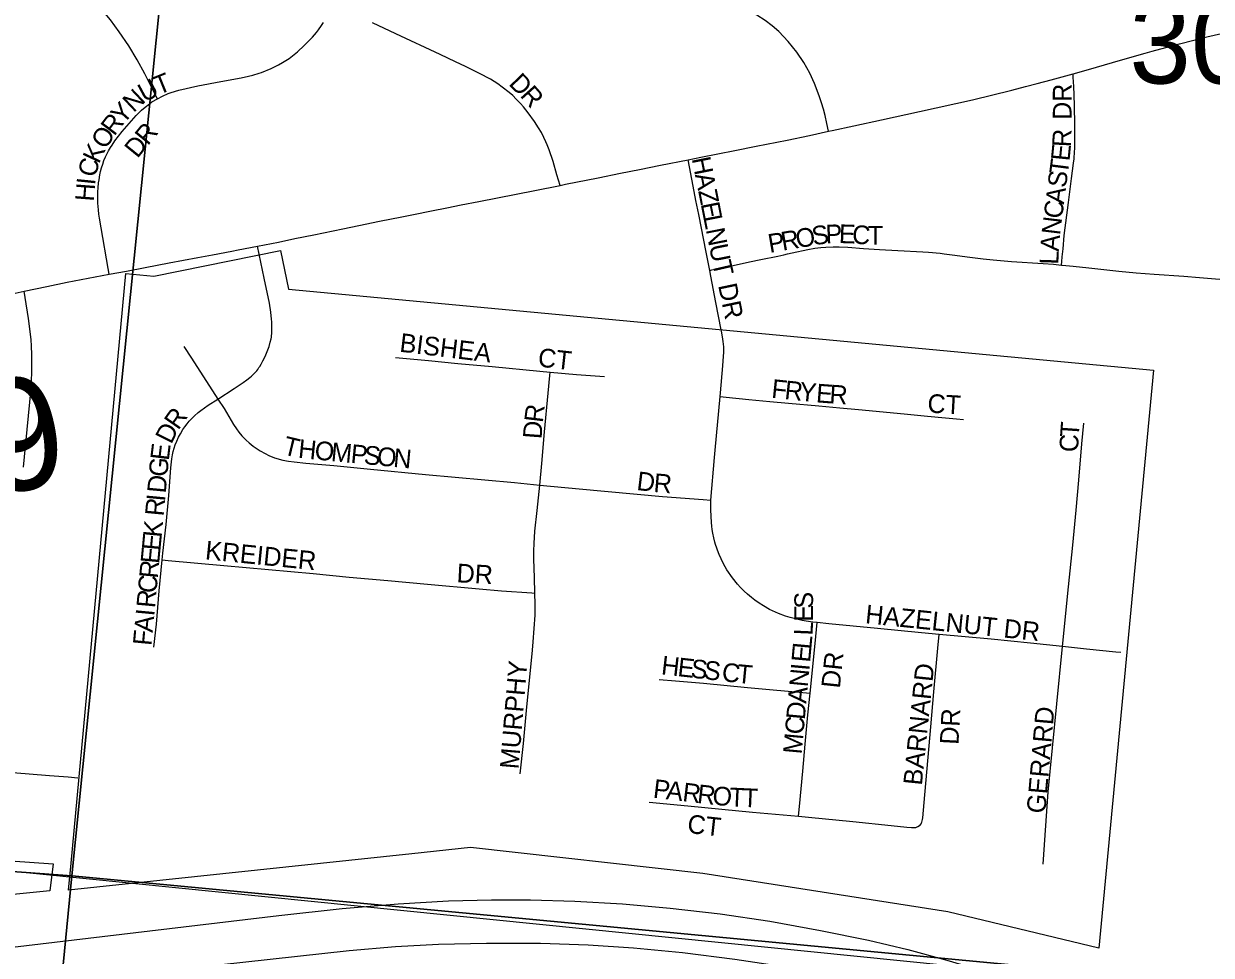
# Model space of a CAD drawing. Extents: x 1410790 to 1770854, y 448063 to 770588.
# Drawn here: x 1535008 to 1538182, y 650649 to 653140 of the extents above; entities that cross this region are included whole.
import ezdxf

# ---------------------------------------------------------------- set-up
doc = ezdxf.new("R2010")
doc.units = 0
for name, color, linetype in [('GM_X_City_Street', 7, 'Continuous'), ('GM_X_City_Street_Text', 7, 'Continuous'), ('GM_X_Corporation', 7, 'Continuous'), ('GM_X_Interstate_Route', 7, 'Continuous'), ('GM_X_Section', 7, 'Continuous'), ('GM_X_Section_Text', 7, 'Continuous'), ('GM_X_Township', 7, 'Continuous'), ('GM_X_Township_Road', 7, 'Continuous'), ('GM_X_Township_Road_Text', 7, 'Continuous'), ('GM_X_Township_Subdivision', 7, 'Continuous'), ('GM_X_Township_Subdivision_Text', 7, 'Continuous')]:
    doc.layers.add(name, color=color, linetype=linetype)

msp = doc.modelspace()

# ---------------------------------------------------------------- linework, layer by layer
at = {"layer": 'GM_X_City_Street'}
for points in [[(1535526.4, 652136.1), (1535569.7, 652164.1), (1535593.9, 652180.3), (1535604.1, 652187.5), (1535612, 652193.4), (1535616.8, 652197.5), (1535622.5, 652203.1), (1535626.4, 652207.4), (1535630.4, 652211.9), (1535632.9, 652215.2), (1535636.4, 652220.1), (1535638.5, 652223.2), (1535642.4, 652229.6), (1535646.9, 652238.3), (1535652.6, 652250), (1535658.5, 652263.3), (1535663.3, 652276.3), (1535666.4, 652287.9), (1535668.8, 652297.4), (1535669.6, 652301.5), (1535670.3, 652306.1), (1535670.7, 652310.2), (1535671.2, 652321.5), (1535671.2, 652328.8), (1535670.6, 652343), (1535670.1, 652349.7), (1535668.1, 652368.1), (1535664.2, 652392.4), (1535650.5, 652458.9), (1535632.2, 652544.9)], [(1536868.9, 652142.8), (1536869.9, 652152.8), (1536876.5, 652225.1), (1536878.1, 652250.8), (1536878.6, 652260.5), (1536878.8, 652267.8), (1536878.8, 652275.5), (1536878.2, 652283.1), (1536877.5, 652290.1), (1536876.7, 652296.3), (1536874.9, 652308), (1536873.2, 652317.4), (1536872.3, 652321.4)], [(1535435.2, 652276.8), (1535455.7, 652245.5), (1535526.4, 652136.1)], [(1536000.9, 652247.4), (1536089.6, 652239), (1536167.9, 652230.9), (1536259.5, 652222.7), (1536387.1, 652210.8), (1536414.8, 652208.1)], [(1536386.9, 651906.3), (1536392.4, 651963.7), (1536399.8, 652048.4), (1536409.5, 652151.6), (1536414, 652199.2), (1536414.8, 652208.1)], [(1536414.8, 652208.1), (1536485.2, 652201.3), (1536560, 652196)], [(1535378, 651705.8), (1535379.8, 651724.2), (1535388, 651801.1), (1535395.2, 651877.9), (1535401.1, 651952.4), (1535403.5, 651975.9), (1535405.1, 651986.6), (1535407.1, 651996), (1535409.6, 652005.1), (1535412.6, 652014), (1535416.7, 652023.9), (1535421.6, 652034.3), (1535426.4, 652043.3), (1535433.1, 652054.5), (1535438.2, 652062.1), (1535444.3, 652070.1), (1535450.1, 652076.9), (1535456.9, 652084.2), (1535464.4, 652091.3), (1535474, 652099.7), (1535480.9, 652105.1), (1535500.9, 652119.6), (1535526.4, 652136.1)], [(1535526.4, 652136.1), (1535543, 652110.5), (1535568.5, 652068.4), (1535576.1, 652056.8), (1535582.7, 652047.8), (1535590.8, 652038.2), (1535602.4, 652025.9), (1535610, 652018.9), (1535620.6, 652010.1), (1535639.6, 651997.3), (1535652.6, 651990.2), (1535662.3, 651985.6), (1535678.1, 651979.1), (1535700.1, 651972.6), (1535715.5, 651970), (1535730.3, 651968.1), (1535761.8, 651964.9), (1535836.8, 651958.2), (1535934.6, 651948.6), (1536081.4, 651934.5), (1536319.7, 651912.9), (1536386.9, 651906.3)], [(1536844.7, 651865.6), (1536854.2, 651979.6), (1536855.6, 651999.2), (1536868.9, 652142.8)], [(1536868.9, 652142.8), (1536885, 652141.2), (1536945.9, 652135), (1537002, 652129.5), (1537051.9, 652125), (1537132.6, 652117.7), (1537189.1, 652112.5), (1537239.2, 652108), (1537360.8, 652096.2), (1537423.3, 652090.2), (1537471.6, 652085.6), (1537500.6, 652083.1), (1537520.1, 652081.5)], [(1537783.9, 651474.4), (1537800.6, 651633.8), (1537812.1, 651745.8), (1537821.3, 651838.8), (1537827.9, 651919.1), (1537836.2, 652016.2), (1537841.2, 652071.6)], [(1536374.1, 651617.3), (1536372.8, 651658.6), (1536371.1, 651708.1), (1536371.4, 651730.5), (1536372.1, 651749.7), (1536374.1, 651783.1), (1536379.9, 651838.4), (1536386.9, 651906.3)], [(1536386.9, 651906.3), (1536492.7, 651896.4), (1536714.9, 651875.8), (1536823.6, 651867.1), (1536844.7, 651865.6)], [(1537128.5, 651538.7), (1537116.7, 651540), (1537098.8, 651542.5), (1537088, 651544.4), (1537070.8, 651548.1), (1537056.6, 651551.8), (1537043.5, 651555.8), (1537025, 651562.5), (1537001.3, 651573.5), (1536984.8, 651583.1), (1536973.6, 651590.1), (1536962.1, 651598.2), (1536952.7, 651605.5), (1536942.2, 651614.3), (1536933.5, 651622.3), (1536923.9, 651632.2), (1536915.3, 651641.6), (1536902.1, 651657.9), (1536887.3, 651679.5), (1536878.3, 651695.7), (1536871.8, 651708.8), (1536866.6, 651720.3), (1536862, 651731.7), (1536860, 651737.5), (1536857, 651746.8), (1536855.1, 651753.6), (1536852.4, 651765.3), (1536849.9, 651777.6), (1536848.2, 651787.4), (1536847, 651796.5), (1536846, 651806.1), (1536845, 651822.9), (1536844.5, 651839.7), (1536844.7, 651865.6)], [(1535355.6, 651472.5), (1535362.2, 651534.6), (1535369.9, 651622.9), (1535378, 651705.8)], [(1535378, 651705.8), (1535393.2, 651704.4), (1535542.2, 651691.2), (1535781.4, 651669.4), (1535877.7, 651660.3), (1535980.9, 651650.7), (1536086.7, 651641.2), (1536224.8, 651628.6), (1536284.3, 651623.5), (1536365.4, 651617.9), (1536374.1, 651617.3)], [(1536335, 651133.8), (1536343.7, 651215.3), (1536352.4, 651313.2), (1536361.4, 651401.3), (1536367.6, 651464.5), (1536369.5, 651486.8), (1536374.4, 651557.9), (1536375, 651587.3), (1536374.1, 651617.3)], [(1537109.6, 651349.7), (1537123.1, 651482.8), (1537126.7, 651519.6), (1537128.5, 651538.7)], [(1537454.3, 651506.5), (1537407.8, 651510.7), (1537290.2, 651522.6), (1537159.6, 651535.4), (1537128.5, 651538.7)], [(1537401.7, 650995.5), (1537403.7, 650997.2), (1537405.5, 650999.1), (1537406.5, 651000.7), (1537407.6, 651002.7), (1537408.5, 651005.2), (1537409.4, 651008.5), (1537410, 651012), (1537410.6, 651016), (1537414.5, 651057.7), (1537432.8, 651259.5), (1537440.8, 651353.1), (1537450.8, 651469.7), (1537454.3, 651506.5)], [(1537783.9, 651474.4), (1537698.5, 651483.5), (1537594, 651493.7), (1537454.3, 651506.5)], [(1537733, 650892.5), (1537746.4, 651085.5), (1537769.3, 651320.9), (1537783.9, 651474.4)], [(1537940, 651458.5), (1537926.9, 651459.6), (1537848.6, 651467.5), (1537783.9, 651474.4)], [(1536706.5, 651385.9), (1536750, 651383), (1536825, 651376.5), (1536942.4, 651365.1), (1537109.6, 651349.7)], [(1537078.2, 651020.8), (1537080.9, 651047), (1537090.5, 651141.3), (1537096.7, 651213.1), (1537103.8, 651291.4), (1537109.6, 651349.7)], [(1536679.7, 651058.3), (1536782.4, 651048.9), (1536873.6, 651039.3), (1536955.4, 651031.9), (1537078.2, 651020.8)], [(1537078.2, 651020.8), (1537105.8, 651018.3), (1537223.5, 651006.9), (1537326.1, 650995.7), (1537368.2, 650991.3), (1537380.4, 650990.3), (1537384.4, 650990.2), (1537388.2, 650990.4), (1537391.9, 650991), (1537394.4, 650991.6), (1537397.9, 650993.2), (1537401.7, 650995.5)]]:
    msp.add_lwpolyline(points, dxfattribs=at)
at = {"layer": 'GM_X_Corporation'}
msp.add_lwpolyline([(1535134.4, 650895.6), (1535280.8, 652471.8), (1535355.4, 652465), (1535694.3, 652533.1), (1535715.1, 652429.8), (1538027.5, 652213.4), (1537881.7, 650667.7), (1537477.9, 650765.2), (1536822.5, 650867.2), (1536201.7, 650937.2), (1536044.9, 650920.6), (1535127.2, 650822.9)], close=True, dxfattribs=at)
msp.add_lwpolyline([(1533375, 651013.4), (1535085.8, 650893.5), (1535077.7, 650821.6), (1534880.1, 650801.4)], dxfattribs=at)
at = {"layer": 'GM_X_Interstate_Route'}
for points in [[(1534796.3, 650649.1), (1535689.1, 650755.7), (1535858.6, 650774.1), (1536008.9, 650786.7), (1536143.1, 650794.3), (1536257.8, 650797.6), (1536362.6, 650797.5), (1536480.5, 650793.9), (1536608.1, 650786.4), (1536735.4, 650775.2), (1536868.9, 650759.5), (1537001.8, 650739.7), (1537137.3, 650715.6), (1537265.7, 650688.9), (1537370.9, 650664), (1537475.3, 650636), (1537623.1, 650592.3), (1537946.2, 650493.1), (1538445.7, 650342.1)], [(1533567.9, 650397.8), (1534167.2, 650465), (1534384.7, 650489.3), (1534681.1, 650525), (1535108, 650573.5), (1535528.1, 650623.8), (1535877.1, 650661.6), (1536001.4, 650672.3), (1536116.2, 650678.7), (1536244.2, 650681.6), (1536388.6, 650681), (1536516.6, 650676.7), (1536637.9, 650669), (1536768.6, 650656.3), (1536908.7, 650638.8), (1537045, 650617.8), (1537167.7, 650595.3), (1537260.8, 650575.3), (1537375.5, 650546.6), (1537517.7, 650506.4), (1537881.9, 650396.3), (1538287.2, 650274.9)]]:
    msp.add_lwpolyline(points, dxfattribs=at)
at = {"layer": 'GM_X_Section'}
for points in [[(1535655.6, 656010.7), (1535136.5, 650861.1), (1529818.7, 651249.1), (1530308.8, 656571.2)], [(1540980.4, 655448.5), (1541102.2, 655436.4), (1540640, 650339.9), (1535136.5, 650861.1), (1535655.6, 656010.7)], [(1535136.5, 650861.1), (1534609.1, 645459.7), (1529389.2, 645957.9), (1529818.7, 651249.1)], [(1540640, 650339.9), (1540107.2, 644974.6), (1534609.1, 645459.7), (1535136.5, 650861.1)]]:
    msp.add_lwpolyline(points, close=True, dxfattribs=at)
at = {"layer": 'GM_X_Township'}
for points in [[(1521201.8, 673511.2), (1520708.9, 668234.8), (1520705, 668192.8), (1520384.1, 664777), (1520023.3, 660938), (1519813.3, 658702.6), (1519702.8, 657525.8), (1519766.8, 657522.5), (1519720.6, 657004.8), (1519314.6, 652452.1), (1524688.8, 651910.7), (1526106.4, 651767.9), (1530096, 651366), (1531112.1, 651263.6), (1532044.4, 651169.7), (1532157.4, 651158.4), (1532426.7, 651131.2), (1533590, 651014), (1540632, 650304.6), (1541201.9, 650247.2), (1548862.1, 649478.6)], [(1518591.2, 644339.7), (1518813, 646827.1), (1519006.1, 648972.3), (1519314.6, 652452.1), (1524688.8, 651910.7), (1526106.4, 651767.9), (1530096, 651366), (1531112.1, 651263.6), (1532044.4, 651169.7), (1532157.4, 651158.4), (1532426.7, 651131.2), (1533590, 651014), (1540632, 650304.6), (1541201.9, 650247.2), (1548862.1, 649478.6), (1553877.2, 648970.1), (1556492.4, 648706.9), (1556030.2, 643461.3)]]:
    msp.add_lwpolyline(points, dxfattribs=at)
at = {"layer": 'GM_X_Township_Road'}
for points in [[(1537812.8, 653005.2), (1537841.8, 653013.7), (1537875.6, 653023.8), (1537939.1, 653042), (1538005, 653060.6), (1538024.3, 653066), (1538097.1, 653085.6), (1538170.2, 653104.5), (1538240.8, 653120.2), (1538289.1, 653129.5)], [(1537158.5, 652852), (1537168.9, 652854.3), (1537226.6, 652866.6), (1537300.1, 652882.5), (1537402.2, 652904.8), (1537544, 652936.2), (1537648.7, 652961.9), (1537685.8, 652971.4), (1537716.2, 652979.5), (1537753.7, 652989.8), (1537812.8, 653005.2)], [(1536783.8, 652775.4), (1536817.9, 652782.5), (1536908.8, 652800.9), (1536965.6, 652812.4), (1537048.2, 652828.7), (1537108, 652841.1), (1537158.5, 652852)], [(1536441.2, 652707.5), (1536455.6, 652710.5), (1536543.1, 652727.8), (1536602.7, 652739.7), (1536653.8, 652750.2), (1536709.4, 652761), (1536783.8, 652775.4)], [(1535688.8, 652556), (1535732.3, 652565), (1535783.4, 652575.4), (1535860.5, 652590.9), (1535903.3, 652600.2), (1535958.3, 652611.8), (1536018.1, 652623.5), (1536049.9, 652629.9), (1536097.6, 652639.6), (1536138.5, 652647.7), (1536176.8, 652655.8), (1536224.5, 652664.6), (1536373.9, 652693.4), (1536441.2, 652707.5)], [(1535282.1, 652478.4), (1535332.1, 652487.6), (1535396.3, 652500.2), (1535472.9, 652514.7), (1535512.2, 652521.8), (1535563.8, 652531.6), (1535580.5, 652534.8), (1535632.2, 652544.9)], [(1535632.2, 652544.9), (1535688.8, 652556)], [(1535008.4, 652424.3), (1535069.3, 652437.1), (1535124, 652448.4), (1535236.2, 652469.7)], [(1535236.2, 652469.7), (1535282.1, 652478.4)], [(1534792.8, 652380.7), (1534883.2, 652398.4), (1534976.3, 652417.5), (1535008.4, 652424.3)]]:
    msp.add_lwpolyline(points, dxfattribs=at)
at = {"layer": 'GM_X_Township_Subdivision'}
for points in [[(1535364.8, 652938.7), (1535360.5, 652946.9), (1535353.3, 652960.7), (1535331.3, 653005.5), (1535311.1, 653043.4), (1535288.9, 653080.1), (1535262.8, 653118.2), (1535239.3, 653150), (1535212.3, 653183.3), (1535107.3, 653300.7), (1535073.9, 653341), (1535051.2, 653370.7), (1535040.4, 653386.3), (1535027.4, 653408.2)], [(1537158.5, 652852), (1537154.4, 652872.8), (1537150.2, 652893.9), (1537145.4, 652911.3), (1537140, 652927.9), (1537134, 652946.6), (1537121.1, 652980.1), (1537109.2, 653007.6), (1537092.5, 653036.3), (1537073.9, 653063.8), (1537051.4, 653092.5), (1537026.1, 653118.9), (1537008.6, 653134.3), (1536989.9, 653148.2), (1536967.4, 653162.4), (1536944.2, 653176.3), (1536862.1, 653216.6), (1536773.5, 653259.8), (1536769.6, 653261.5)], [(1535364.8, 652938.7), (1535378.8, 652945.9), (1535393.8, 652953.1), (1535401.9, 652955.9), (1535422.1, 652961.9), (1535473.1, 652973.1), (1535534, 652985.2), (1535588.9, 652994.7), (1535608.6, 652999.3), (1535619.9, 653002.3), (1535636.7, 653007.3), (1535643, 653009.5), (1535668.9, 653019.7), (1535688.3, 653029.4), (1535699.3, 653035.5), (1535717, 653046.9), (1535730.3, 653057), (1535739.4, 653064.7), (1535757.3, 653081.3), (1535779.4, 653103.6), (1535789.8, 653115.8), (1535795.6, 653123.3), (1535803.6, 653134.8), (1535808.9, 653142.9)], [(1536441.2, 652707.5), (1536433, 652735.5), (1536422.6, 652771.1), (1536412, 652802), (1536406.8, 652815.7), (1536403.2, 652824.2), (1536398, 652835.4), (1536391.3, 652848.4), (1536384, 652861.1), (1536372.5, 652878.6), (1536355.8, 652901.7), (1536343.4, 652917), (1536335.6, 652926), (1536324.3, 652938.1), (1536314.9, 652947.3), (1536305.4, 652955.9), (1536286.7, 652970.3), (1536275, 652978.7), (1536255.2, 652991), (1536226.3, 653006.5), (1536188.7, 653025.5), (1536162.1, 653037.9), (1536120.8, 653057.4), (1536001.8, 653112.5), (1535939.7, 653142.3)], [(1537781.3, 652494.5), (1537782.3, 652503.9), (1537783.6, 652516.3), (1537785.8, 652538), (1537789.2, 652573.8), (1537800, 652661.5), (1537808.5, 652725.8), (1537813.9, 652767), (1537815.3, 652778.4), (1537815.8, 652784.7), (1537816.3, 652791.5), (1537816.7, 652798.3), (1537817.1, 652805.3), (1537817.3, 652813.7), (1537817.5, 652821.3), (1537817.5, 652830.3), (1537817.3, 652869.2), (1537816.3, 652920.5), (1537815.4, 652949.2), (1537814.5, 652971.9), (1537813, 652996.3), (1537812.8, 653005.2)], [(1535236.2, 652469.7), (1535233.4, 652485.3), (1535214.4, 652594.3), (1535210.2, 652619.4), (1535208.6, 652630.7), (1535207.4, 652642), (1535206, 652660.2), (1535205.4, 652675.9), (1535205.5, 652690.2), (1535206.1, 652701), (1535207.5, 652714), (1535208.8, 652722.6), (1535211.3, 652735.7), (1535213.1, 652744.7), (1535215.6, 652753.9), (1535218.6, 652764), (1535222.1, 652773.9), (1535226, 652783.7), (1535231.4, 652794.5), (1535234.3, 652799.7), (1535239.9, 652809.1), (1535243.9, 652815.3), (1535251.3, 652826.2), (1535260.8, 652838.8), (1535270.6, 652851), (1535308.2, 652893.9), (1535322.7, 652908.2), (1535332.5, 652916.9), (1535343.4, 652925.7), (1535350.1, 652930.6), (1535364.8, 652938.7)], [(1536841.3, 652480), (1536831.9, 652529.1), (1536811.8, 652629.6), (1536804.1, 652666.9), (1536796.8, 652705.4), (1536783.8, 652775.4)], [(1536841.3, 652480), (1536847, 652481.2), (1536879.7, 652487.8), (1536947.2, 652502.6), (1536978.3, 652509.2), (1537023.4, 652518.5), (1537039.3, 652522), (1537048.8, 652524.1), (1537061.5, 652526.9), (1537103.6, 652535.8), (1537122.7, 652539.4), (1537130.7, 652540.7), (1537138.6, 652541.6), (1537151.3, 652542.6), (1537171.3, 652543.1), (1537187.6, 652543.3), (1537210.9, 652542.3), (1537252.5, 652539), (1537295.5, 652536.1), (1537344.5, 652533.7), (1537410.8, 652530.1), (1537426, 652528.8), (1537457, 652526), (1537467.7, 652524.6), (1537496.3, 652520.5), (1537529.5, 652515.9), (1537572.5, 652511.1), (1537599.2, 652508.5), (1537647.7, 652504), (1537732.8, 652498.4), (1537760.6, 652496.5), (1537781.3, 652494.5)], [(1536872.3, 652321.4), (1536857.9, 652394.6), (1536844.3, 652464.9), (1536841.3, 652480)], [(1537781.3, 652494.5), (1537783.4, 652494.3), (1537813, 652491.4), (1537854.3, 652486.9), (1537902.5, 652481.9), (1537935.2, 652478.2), (1537981.2, 652473.9), (1538029.5, 652470.2), (1538108.6, 652464.8), (1538150.8, 652461.1), (1538192.9, 652457.7), (1538239, 652453.6)], [(1535006.8, 651953.8), (1535009.4, 651981.6), (1535027.2, 652164.3), (1535029.1, 652207.1), (1535029.4, 652222.1), (1535029.2, 652254.5), (1535028.3, 652278.4), (1535027.2, 652294.5), (1535025.7, 652309.2), (1535019.9, 652351.8), (1535011.1, 652407.4), (1535008.4, 652424.3)], [(1534926.9, 651141.6), (1534978.6, 651137.5), (1535076.8, 651129.9), (1535125.9, 651125.6), (1535151.8, 651123.4)]]:
    msp.add_lwpolyline(points, dxfattribs=at)

# ---------------------------------------------------------------- texts
at = {"layer": 'GM_X_City_Street_Text'}
for s, rotation, p in [('BISHEA', 353.1568, (1536010.6, 652262.9)), ('CT', 353.6558, (1536380.4, 652223.2)), ('F', 354.1154, (1537004.8, 652139.7)), ('R', 354.113, (1537039.8, 652136.1)), ('Y', 354.272, (1537079.4, 652132)), ('E', 355.6442, (1537124.4, 652127.5)), ('R', 356.3733, (1537160.2, 652124.8)), ('CT', 356.8219, (1537422.4, 652100.1)), ('R', 83.1611, (1536394.9, 652071.4)), ('R', 54.9861, (1535420.4, 652051.1)), ('D', 63.3567, (1535401.7, 652013.4)), ('D', 85.6901, (1536391.6, 652028.1)), ('T', 85.9261, (1537827.5, 652032.6)), ('T', 346.262, (1535697.9, 651988.9)), ('H', 354.2538, (1535739.6, 651979.2)), ('O', 354.6147, (1535783.7, 651974.8)), ('M', 354.6011, (1535827.5, 651970.6)), ('C', 87.8506, (1537826, 651993.4)), ('E', 83.18, (1535395.2, 651970.1)), ('P', 354.6052, (1535880.1, 651965.7)), ('S', 354.6102, (1535915.2, 651962.4)), ('O', 354.5939, (1535950.2, 651959.1)), ('N', 354.6088, (1535994, 651954.9)), ('G', 84.6482, (1535391.2, 651926.7)), ('D', 84.6484, (1535387.1, 651882.9)), ('D', 353.165, (1536644.3, 651893.2)), ('R', 355.301, (1536690, 651887.8)), ('R', 84.6489, (1535381.3, 651821.5)), ('I', 84.6374, (1535385, 651861)), ('K', 84.6484, (1535376, 651764.6)), ('E', 84.6374, (1535372.7, 651729.5)), ('E', 84.651, (1535369.4, 651694.5)), ('KREIDER', 354.2925, (1535491.1, 651707.8)), ('R', 84.6489, (1535365.7, 651655.1)), ('DR', 356.989, (1536163.9, 651646.3)), ('C', 84.6374, (1535362, 651615.6)), ('R', 84.6495, (1535358.3, 651576.2)), ('S', 89.9956, (1537117.6, 651576)), ('E', 89.8823, (1537117.6, 651540.7)), ('HAZELNUT DR', 354.1139, (1537255.6, 651536.9)), ('A', 84.6374, (1535352.2, 651510.5)), ('I', 84.6502, (1535356.3, 651554.3)), ('F', 84.651, (1535348.9, 651475.4)), ('L', 87.5048, (1537116, 651503.3)), ('L', 84.7574, (1537112.6, 651465.6)), ('H', 353.5826, (1536710.1, 651400.4)), ('E', 84.7574, (1537109.4, 651430.6)), ('DR', 83.9877, (1537189.1, 651361.2)), ('MURPHY', 85.2385, (1536330.1, 651145.4)), ('E', 353.5663, (1536753.8, 651395.5)), ('S', 353.5987, (1536788.9, 651391.6)), ('S', 353.5663, (1536823.8, 651387.7)), ('C', 353.5753, (1536871.9, 651382.2)), ('T', 354.5167, (1536912.2, 651377.7)), ('I', 84.7607, (1537107.4, 651408.6)), ('BARNARD', 84.1227, (1537408.3, 651101.7)), ('N', 84.7555, (1537103.4, 651364.8)), ('A', 84.7571, (1537099.3, 651321)), ('D', 84.7727, (1537095.3, 651277.2)), ('DR', 86.9827, (1537506.2, 651211.1)), ('GERARD', 84.988, (1537738.1, 651026.7)), ('C', 84.7564, (1537091.7, 651237.8)), ('M', 84.7569, (1537086.9, 651185.2)), ('P', 353.2359, (1536688.2, 651070.5)), ('A', 353.2366, (1536723.1, 651066.3)), ('R', 353.2334, (1536766.8, 651061.2)), ('R', 353.225, (1536806.1, 651056.5)), ('O', 354.8963, (1536847, 651051.7)), ('T', 357.1757, (1536893, 651047.6)), ('T', 357.2572, (1536928.3, 651045.9)), ('CT', 353.6631, (1536779.8, 650976.2))]:
    msp.add_text(s, height=50, rotation=rotation, dxfattribs=at).set_placement(p)
at = {"layer": 'GM_X_Section_Text'}
msp.add_text('30', height=221, rotation=0, dxfattribs=at).set_placement((1537963.1, 652979.8))
at = {"layer": 'GM_X_Township_Road_Text'}
msp.add_text('T-119', height=300, rotation=11.8479, dxfattribs=at).set_placement((1534114.3, 651704.3))
at = {"layer": 'GM_X_Township_Subdivision_Text'}
for s, rotation, p in [('T', 22.1007, (1535367.9, 652948.6)), ('D', 314.2736, (1536302, 652977.5)), ('U', 28.2808, (1535330.4, 652928.4)), ('R', 311.7868, (1536332.3, 652946.4)), ('DR', 90, (1537808.5, 652882.7)), ('N', 43.2999, (1535301.2, 652900.2)), ('Y', 48.3329, (1535272.8, 652868.2)), ('R', 52.829, (1535249.5, 652837.4)), ('O', 57.1072, (1535226.2, 652801.3)), ('R', 50.608, (1535339.1, 652811.9)), ('R', 87.4867, (1537806.6, 652808.9)), ('K', 64.9501, (1535208.4, 652763)), ('D', 50.9136, (1535311.4, 652777.8)), ('E', 84.3891, (1537802.9, 652771)), ('H', 281.2092, (1536793.1, 652779)), ('C', 76.5704, (1535200.1, 652727)), ('T', 82.6446, (1537798.3, 652734.4)), ('I', 84.1763, (1535198.2, 652706.9)), ('A', 281.2092, (1536801.6, 652735.8)), ('S', 82.6413, (1537793.7, 652699.5)), ('H', 85.6465, (1535194.8, 652663.3)), ('Z', 281.2055, (1536810.2, 652692.7)), ('A', 82.6364, (1537788.1, 652655.8)), ('E', 281.2052, (1536817, 652658.2)), ('C', 82.6701, (1537783.1, 652616.6)), ('L', 281.2055, (1536823.9, 652623.6)), ('N', 281.2092, (1536830.7, 652589.1)), ('O', 9.6636, (1537075.4, 652539.2)), ('S', 9.2737, (1537118.6, 652546.6)), ('P', 1.8855, (1537151.7, 652552.1)), ('E', 358.0872, (1537186, 652553.3)), ('C', 355.9412, (1537220.7, 652552.1)), ('T', 359.6126, (1537263.7, 652549.2)), ('N', 83.1433, (1537777.8, 652573)), ('P', 9.6622, (1537001.6, 652526.7)), ('R', 9.6581, (1537036.3, 652532.6)), ('A', 85.3834, (1537774.3, 652529.6)), ('U', 281.2092, (1536839.3, 652546)), ('L', 88.1691, (1537773.2, 652495.1)), ('T', 282.8517, (1536848.2, 652501.3)), ('DR', 281.8927, (1536863.5, 652440.3))]:
    msp.add_text(s, height=50, rotation=rotation, dxfattribs=at).set_placement(p)

doc.saveas('drawing.dxf')
